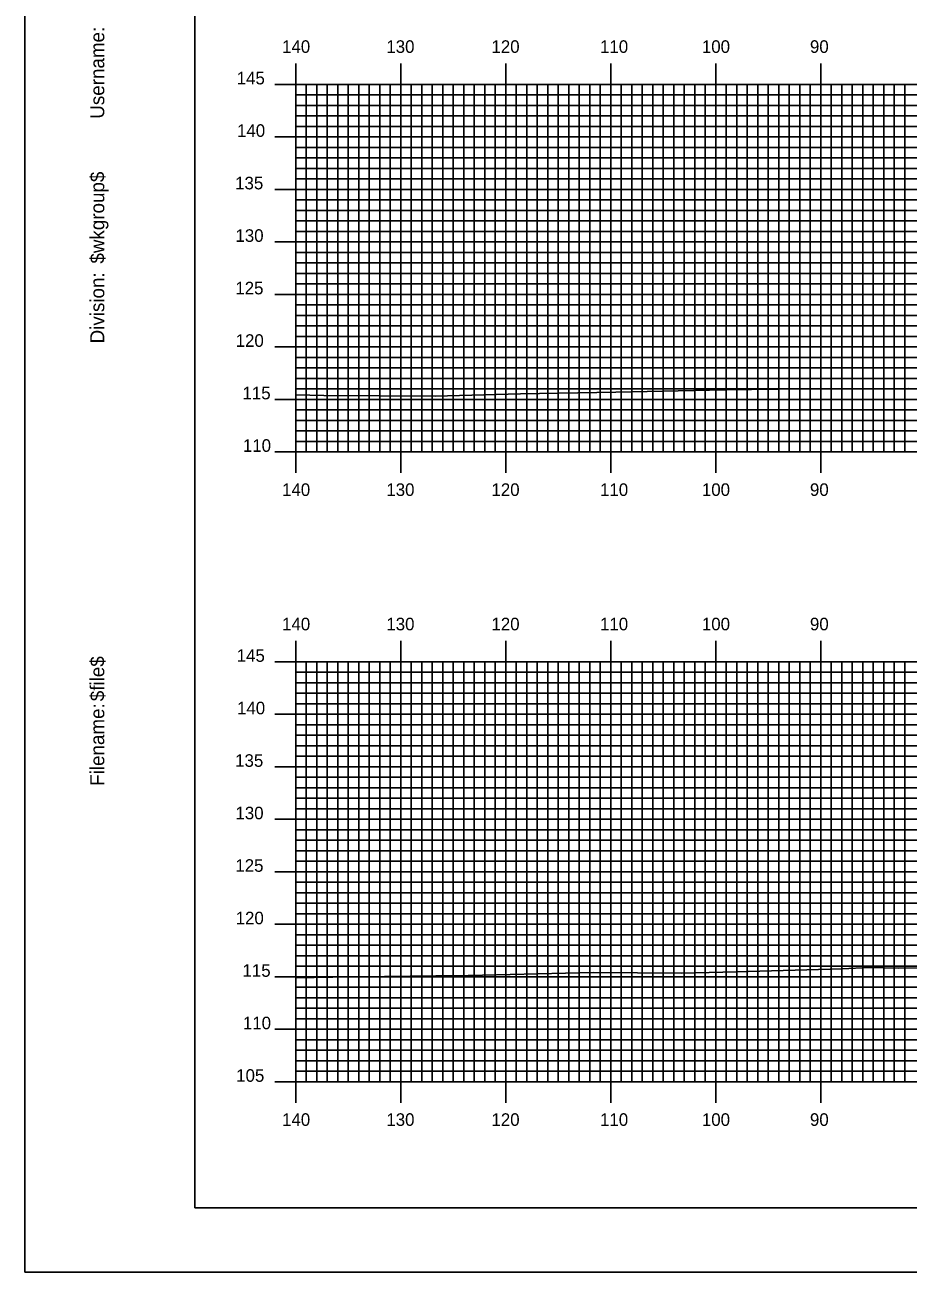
# Model space of a CAD drawing. Extents: x 1789337 to 1789680, y 442591 to 442811.
# Drawn here: x 1789336.9 to 1789421, y 442590.5 to 442709.3 of the extents above; entities that cross this region are included whole.
import ezdxf

# ---------------------------------------------------------------- set-up
doc = ezdxf.new("R2010")
doc.units = 0
for name, color, linetype in [('BORDER', 7, 'Continuous'), ('H_V ANNOTATION', 7, 'Continuous'), ('MAJOR', 7, 'Continuous'), ('MINOR', 7, 'Continuous'), ('PLOT BOUNDARY', 7, 'Continuous'), ('S_Roadway_Centerline', 7, 'Continuous')]:
    doc.layers.add(name, color=color, linetype=linetype)

msp = doc.modelspace()

# ---------------------------------------------------------------- linework, layer by layer
at = {"layer": 'BORDER'}
msp.add_lwpolyline([(1789353.07, 442596.67), (1789673.07, 442596.67), (1789673.07, 442806.67), (1789353.07, 442806.67)], close=True, dxfattribs=at)
at = {"layer": 'MAJOR'}
for p, q in [((1789362.67, 442705.67), (1789362.67, 442703.67)), ((1789372.67, 442705.67), (1789372.67, 442703.67)), ((1789382.67, 442705.67), (1789382.67, 442703.67)), ((1789392.67, 442705.67), (1789392.67, 442703.67)), ((1789402.67, 442705.67), (1789402.67, 442703.67)), ((1789412.67, 442705.67), (1789412.67, 442703.67)), ((1789360.67, 442703.67), (1789362.67, 442703.67)), ((1789362.67, 442703.67), (1789642.67, 442703.67)), ((1789362.67, 442668.67), (1789362.67, 442703.67)), ((1789362.67, 442668.67), (1789362.67, 442703.67)), ((1789362.67, 442703.67), (1789642.67, 442703.67)), ((1789372.67, 442668.67), (1789372.67, 442703.67)), ((1789382.67, 442668.67), (1789382.67, 442703.67)), ((1789392.67, 442668.67), (1789392.67, 442703.67)), ((1789402.67, 442668.67), (1789402.67, 442703.67)), ((1789412.67, 442668.67), (1789412.67, 442703.67)), ((1789360.67, 442698.67), (1789362.67, 442698.67)), ((1789362.67, 442698.67), (1789642.67, 442698.67)), ((1789360.67, 442693.67), (1789362.67, 442693.67)), ((1789362.67, 442693.67), (1789642.67, 442693.67)), ((1789360.67, 442688.67), (1789362.67, 442688.67)), ((1789362.67, 442688.67), (1789642.67, 442688.67)), ((1789360.67, 442683.67), (1789362.67, 442683.67)), ((1789362.67, 442683.67), (1789642.67, 442683.67)), ((1789360.67, 442678.67), (1789362.67, 442678.67)), ((1789362.67, 442678.67), (1789642.67, 442678.67)), ((1789360.67, 442673.67), (1789362.67, 442673.67)), ((1789362.67, 442673.67), (1789642.67, 442673.67)), ((1789360.67, 442668.67), (1789362.67, 442668.67)), ((1789362.67, 442668.67), (1789642.67, 442668.67)), ((1789362.67, 442668.67), (1789642.67, 442668.67)), ((1789362.67, 442666.66), (1789362.67, 442668.67)), ((1789372.67, 442666.66), (1789372.67, 442668.67)), ((1789382.67, 442666.66), (1789382.67, 442668.67)), ((1789392.67, 442666.66), (1789392.67, 442668.67)), ((1789402.67, 442666.66), (1789402.67, 442668.67)), ((1789412.67, 442666.66), (1789412.67, 442668.67)), ((1789362.67, 442650.67), (1789362.67, 442648.67)), ((1789372.67, 442650.67), (1789372.67, 442648.67)), ((1789382.67, 442650.67), (1789382.67, 442648.67)), ((1789392.67, 442650.67), (1789392.67, 442648.67)), ((1789402.67, 442650.67), (1789402.67, 442648.67)), ((1789412.67, 442650.67), (1789412.67, 442648.67)), ((1789360.67, 442648.67), (1789362.67, 442648.67)), ((1789362.67, 442648.67), (1789642.67, 442648.67)), ((1789362.67, 442608.67), (1789362.67, 442648.67)), ((1789362.67, 442608.67), (1789362.67, 442648.67)), ((1789362.67, 442648.67), (1789642.67, 442648.67)), ((1789372.67, 442608.67), (1789372.67, 442648.67)), ((1789382.67, 442608.67), (1789382.67, 442648.67)), ((1789392.67, 442608.67), (1789392.67, 442648.67)), ((1789402.67, 442608.67), (1789402.67, 442648.67)), ((1789412.67, 442608.67), (1789412.67, 442648.67)), ((1789360.67, 442643.67), (1789362.67, 442643.67)), ((1789362.67, 442643.67), (1789642.67, 442643.67)), ((1789360.67, 442638.67), (1789362.67, 442638.67)), ((1789362.67, 442638.67), (1789642.67, 442638.67)), ((1789360.67, 442633.67), (1789362.67, 442633.67)), ((1789362.67, 442633.67), (1789642.67, 442633.67)), ((1789360.67, 442628.67), (1789362.67, 442628.67)), ((1789362.67, 442628.67), (1789642.67, 442628.67)), ((1789360.67, 442623.67), (1789362.67, 442623.67)), ((1789362.67, 442623.67), (1789642.67, 442623.67)), ((1789360.67, 442618.67), (1789362.67, 442618.67)), ((1789362.67, 442618.67), (1789642.67, 442618.67)), ((1789360.67, 442613.67), (1789362.67, 442613.67)), ((1789362.67, 442613.67), (1789642.67, 442613.67)), ((1789360.67, 442608.67), (1789362.67, 442608.67)), ((1789362.67, 442608.67), (1789642.67, 442608.67)), ((1789362.67, 442608.67), (1789642.67, 442608.67)), ((1789362.67, 442606.66), (1789362.67, 442608.67)), ((1789372.67, 442606.66), (1789372.67, 442608.67)), ((1789382.67, 442606.66), (1789382.67, 442608.67)), ((1789392.67, 442606.66), (1789392.67, 442608.67)), ((1789402.67, 442606.66), (1789402.67, 442608.67)), ((1789412.67, 442606.66), (1789412.67, 442608.67))]:
    msp.add_line(p, q, dxfattribs=at)
at = {"layer": 'MINOR'}
for p, q in [((1789362.67, 442702.67), (1789642.67, 442702.67)), ((1789362.67, 442702.67), (1789364.67, 442702.67)), ((1789363.67, 442668.67), (1789363.67, 442703.67)), ((1789364.67, 442668.67), (1789364.67, 442703.67)), ((1789365.67, 442668.67), (1789365.67, 442703.67)), ((1789366.67, 442668.67), (1789366.67, 442703.67)), ((1789367.67, 442668.67), (1789367.67, 442703.67)), ((1789368.67, 442668.67), (1789368.67, 442703.67)), ((1789369.67, 442668.67), (1789369.67, 442703.67)), ((1789370.67, 442668.67), (1789370.67, 442703.67)), ((1789371.67, 442668.67), (1789371.67, 442703.67)), ((1789373.67, 442668.67), (1789373.67, 442703.67)), ((1789374.67, 442668.67), (1789374.67, 442703.67)), ((1789375.67, 442668.67), (1789375.67, 442703.67)), ((1789376.67, 442668.67), (1789376.67, 442703.67)), ((1789377.67, 442668.67), (1789377.67, 442703.67)), ((1789378.67, 442668.67), (1789378.67, 442703.67)), ((1789379.67, 442668.67), (1789379.67, 442703.67)), ((1789380.67, 442668.67), (1789380.67, 442703.67)), ((1789381.67, 442668.67), (1789381.67, 442703.67)), ((1789383.67, 442668.67), (1789383.67, 442703.67)), ((1789384.67, 442668.67), (1789384.67, 442703.67)), ((1789385.67, 442668.67), (1789385.67, 442703.67)), ((1789386.67, 442668.67), (1789386.67, 442703.67)), ((1789387.67, 442668.67), (1789387.67, 442703.67)), ((1789388.67, 442668.67), (1789388.67, 442703.67)), ((1789389.67, 442668.67), (1789389.67, 442703.67)), ((1789390.67, 442668.67), (1789390.67, 442703.67)), ((1789391.67, 442668.67), (1789391.67, 442703.67)), ((1789393.67, 442668.67), (1789393.67, 442703.67)), ((1789394.67, 442668.67), (1789394.67, 442703.67)), ((1789395.67, 442668.67), (1789395.67, 442703.67)), ((1789396.67, 442668.67), (1789396.67, 442703.67)), ((1789397.67, 442668.67), (1789397.67, 442703.67)), ((1789398.67, 442668.67), (1789398.67, 442703.67)), ((1789399.67, 442668.67), (1789399.67, 442703.67)), ((1789400.67, 442668.67), (1789400.67, 442703.67)), ((1789401.67, 442668.67), (1789401.67, 442703.67)), ((1789403.67, 442668.67), (1789403.67, 442703.67)), ((1789404.67, 442668.67), (1789404.67, 442703.67)), ((1789405.67, 442668.67), (1789405.67, 442703.67)), ((1789406.67, 442668.67), (1789406.67, 442703.67)), ((1789407.67, 442668.67), (1789407.67, 442703.67)), ((1789408.67, 442668.67), (1789408.67, 442703.67)), ((1789409.67, 442668.67), (1789409.67, 442703.67)), ((1789410.67, 442668.67), (1789410.67, 442703.67)), ((1789411.67, 442668.67), (1789411.67, 442703.67)), ((1789413.67, 442668.67), (1789413.67, 442703.67)), ((1789414.67, 442668.67), (1789414.67, 442703.67)), ((1789415.67, 442668.67), (1789415.67, 442703.67)), ((1789416.67, 442668.67), (1789416.67, 442703.67)), ((1789417.67, 442668.67), (1789417.67, 442703.67)), ((1789418.67, 442668.67), (1789418.67, 442703.67)), ((1789419.67, 442668.67), (1789419.67, 442703.67)), ((1789420.67, 442668.67), (1789420.67, 442703.67)), ((1789362.67, 442701.67), (1789642.67, 442701.67)), ((1789362.67, 442701.67), (1789364.67, 442701.67)), ((1789362.67, 442700.67), (1789642.67, 442700.67)), ((1789362.67, 442700.67), (1789364.67, 442700.67)), ((1789362.67, 442699.67), (1789642.67, 442699.67)), ((1789362.67, 442699.67), (1789364.67, 442699.67)), ((1789362.67, 442697.67), (1789642.67, 442697.67)), ((1789362.67, 442697.67), (1789364.67, 442697.67)), ((1789362.67, 442696.67), (1789642.67, 442696.67)), ((1789362.67, 442696.67), (1789364.67, 442696.67)), ((1789362.67, 442695.67), (1789642.67, 442695.67)), ((1789362.67, 442695.67), (1789364.67, 442695.67)), ((1789362.67, 442694.67), (1789642.67, 442694.67)), ((1789362.67, 442694.67), (1789364.67, 442694.67)), ((1789362.67, 442692.67), (1789642.67, 442692.67)), ((1789362.67, 442692.67), (1789364.67, 442692.67)), ((1789362.67, 442691.67), (1789642.67, 442691.67)), ((1789362.67, 442691.67), (1789364.67, 442691.67)), ((1789362.67, 442690.67), (1789642.67, 442690.67)), ((1789362.67, 442690.67), (1789364.67, 442690.67)), ((1789362.67, 442689.67), (1789642.67, 442689.67)), ((1789362.67, 442689.67), (1789364.67, 442689.67)), ((1789362.67, 442687.67), (1789642.67, 442687.67)), ((1789362.67, 442687.67), (1789364.67, 442687.67)), ((1789362.67, 442686.67), (1789642.67, 442686.67)), ((1789362.67, 442686.67), (1789364.67, 442686.67)), ((1789362.67, 442685.67), (1789642.67, 442685.67)), ((1789362.67, 442685.67), (1789364.67, 442685.67)), ((1789362.67, 442684.67), (1789642.67, 442684.67)), ((1789362.67, 442684.67), (1789364.67, 442684.67)), ((1789362.67, 442682.67), (1789642.67, 442682.67)), ((1789362.67, 442682.67), (1789364.67, 442682.67)), ((1789362.67, 442681.67), (1789642.67, 442681.67)), ((1789362.67, 442681.67), (1789364.67, 442681.67)), ((1789362.67, 442680.67), (1789642.67, 442680.67)), ((1789362.67, 442680.67), (1789364.67, 442680.67)), ((1789362.67, 442679.67), (1789642.67, 442679.67)), ((1789362.67, 442679.67), (1789364.67, 442679.67)), ((1789362.67, 442677.67), (1789642.67, 442677.67)), ((1789362.67, 442677.67), (1789364.67, 442677.67)), ((1789362.67, 442676.67), (1789642.67, 442676.67)), ((1789362.67, 442676.67), (1789364.67, 442676.67)), ((1789362.67, 442675.67), (1789642.67, 442675.67)), ((1789362.67, 442675.67), (1789364.67, 442675.67)), ((1789362.67, 442674.67), (1789642.67, 442674.67)), ((1789362.67, 442674.67), (1789364.67, 442674.67)), ((1789362.67, 442672.67), (1789642.67, 442672.67)), ((1789362.67, 442672.67), (1789364.67, 442672.67)), ((1789362.67, 442671.67), (1789642.67, 442671.67)), ((1789362.67, 442671.67), (1789364.67, 442671.67)), ((1789362.67, 442670.67), (1789642.67, 442670.67)), ((1789362.67, 442670.67), (1789364.67, 442670.67)), ((1789362.67, 442669.67), (1789642.67, 442669.67)), ((1789362.67, 442669.67), (1789364.67, 442669.67)), ((1789363.67, 442608.67), (1789363.67, 442648.67)), ((1789364.67, 442608.67), (1789364.67, 442648.67)), ((1789365.67, 442608.67), (1789365.67, 442648.67)), ((1789366.67, 442608.67), (1789366.67, 442648.67)), ((1789367.67, 442608.67), (1789367.67, 442648.67)), ((1789368.67, 442608.67), (1789368.67, 442648.67)), ((1789369.67, 442608.67), (1789369.67, 442648.67)), ((1789370.67, 442608.67), (1789370.67, 442648.67)), ((1789371.67, 442608.67), (1789371.67, 442648.67)), ((1789373.67, 442608.67), (1789373.67, 442648.67)), ((1789374.67, 442608.67), (1789374.67, 442648.67)), ((1789375.67, 442608.67), (1789375.67, 442648.67)), ((1789376.67, 442608.67), (1789376.67, 442648.67)), ((1789377.67, 442608.67), (1789377.67, 442648.67)), ((1789378.67, 442608.67), (1789378.67, 442648.67)), ((1789379.67, 442608.67), (1789379.67, 442648.67)), ((1789380.67, 442608.67), (1789380.67, 442648.67)), ((1789381.67, 442608.67), (1789381.67, 442648.67)), ((1789383.67, 442608.67), (1789383.67, 442648.67)), ((1789384.67, 442608.67), (1789384.67, 442648.67)), ((1789385.67, 442608.67), (1789385.67, 442648.67)), ((1789386.67, 442608.67), (1789386.67, 442648.67)), ((1789387.67, 442608.67), (1789387.67, 442648.67)), ((1789388.67, 442608.67), (1789388.67, 442648.67)), ((1789389.67, 442608.67), (1789389.67, 442648.67)), ((1789390.67, 442608.67), (1789390.67, 442648.67)), ((1789391.67, 442608.67), (1789391.67, 442648.67)), ((1789393.67, 442608.67), (1789393.67, 442648.67)), ((1789394.67, 442608.67), (1789394.67, 442648.67)), ((1789395.67, 442608.67), (1789395.67, 442648.67)), ((1789396.67, 442608.67), (1789396.67, 442648.67)), ((1789397.67, 442608.67), (1789397.67, 442648.67)), ((1789398.67, 442608.67), (1789398.67, 442648.67)), ((1789399.67, 442608.67), (1789399.67, 442648.67)), ((1789400.67, 442608.67), (1789400.67, 442648.67)), ((1789401.67, 442608.67), (1789401.67, 442648.67)), ((1789403.67, 442608.67), (1789403.67, 442648.67)), ((1789404.67, 442608.67), (1789404.67, 442648.67)), ((1789405.67, 442608.67), (1789405.67, 442648.67)), ((1789406.67, 442608.67), (1789406.67, 442648.67)), ((1789407.67, 442608.67), (1789407.67, 442648.67)), ((1789408.67, 442608.67), (1789408.67, 442648.67)), ((1789409.67, 442608.67), (1789409.67, 442648.67)), ((1789410.67, 442608.67), (1789410.67, 442648.67)), ((1789411.67, 442608.67), (1789411.67, 442648.67)), ((1789413.67, 442608.67), (1789413.67, 442648.67)), ((1789414.67, 442608.67), (1789414.67, 442648.67)), ((1789415.67, 442608.67), (1789415.67, 442648.67)), ((1789416.67, 442608.67), (1789416.67, 442648.67)), ((1789417.67, 442608.67), (1789417.67, 442648.67)), ((1789418.67, 442608.67), (1789418.67, 442648.67)), ((1789419.67, 442608.67), (1789419.67, 442648.67)), ((1789420.67, 442608.67), (1789420.67, 442648.67)), ((1789362.67, 442647.67), (1789642.67, 442647.67)), ((1789362.67, 442647.67), (1789364.67, 442647.67)), ((1789362.67, 442646.67), (1789642.67, 442646.67)), ((1789362.67, 442646.67), (1789364.67, 442646.67)), ((1789362.67, 442645.67), (1789642.67, 442645.67)), ((1789362.67, 442645.67), (1789364.67, 442645.67)), ((1789362.67, 442644.67), (1789642.67, 442644.67)), ((1789362.67, 442644.67), (1789364.67, 442644.67)), ((1789362.67, 442642.67), (1789642.67, 442642.67)), ((1789362.67, 442642.67), (1789364.67, 442642.67)), ((1789362.67, 442641.67), (1789642.67, 442641.67)), ((1789362.67, 442641.67), (1789364.67, 442641.67)), ((1789362.67, 442640.67), (1789642.67, 442640.67)), ((1789362.67, 442640.67), (1789364.67, 442640.67)), ((1789362.67, 442639.67), (1789642.67, 442639.67)), ((1789362.67, 442639.67), (1789364.67, 442639.67)), ((1789362.67, 442637.67), (1789642.67, 442637.67)), ((1789362.67, 442637.67), (1789364.67, 442637.67)), ((1789362.67, 442636.67), (1789642.67, 442636.67)), ((1789362.67, 442636.67), (1789364.67, 442636.67)), ((1789362.67, 442635.67), (1789642.67, 442635.67)), ((1789362.67, 442635.67), (1789364.67, 442635.67)), ((1789362.67, 442634.67), (1789642.67, 442634.67)), ((1789362.67, 442634.67), (1789364.67, 442634.67)), ((1789362.67, 442632.67), (1789642.67, 442632.67)), ((1789362.67, 442632.67), (1789364.67, 442632.67)), ((1789362.67, 442631.67), (1789642.67, 442631.67)), ((1789362.67, 442631.67), (1789364.67, 442631.67)), ((1789362.67, 442630.67), (1789642.67, 442630.67)), ((1789362.67, 442630.67), (1789364.67, 442630.67)), ((1789362.67, 442629.67), (1789642.67, 442629.67)), ((1789362.67, 442629.67), (1789364.67, 442629.67)), ((1789362.67, 442627.67), (1789642.67, 442627.67)), ((1789362.67, 442627.67), (1789364.67, 442627.67)), ((1789362.67, 442626.67), (1789642.67, 442626.67)), ((1789362.67, 442626.67), (1789364.67, 442626.67)), ((1789362.67, 442625.67), (1789642.67, 442625.67)), ((1789362.67, 442625.67), (1789364.67, 442625.67)), ((1789362.67, 442624.67), (1789642.67, 442624.67)), ((1789362.67, 442624.67), (1789364.67, 442624.67)), ((1789362.67, 442622.67), (1789642.67, 442622.67)), ((1789362.67, 442622.67), (1789364.67, 442622.67)), ((1789362.67, 442621.67), (1789642.67, 442621.67)), ((1789362.67, 442621.67), (1789364.67, 442621.67)), ((1789362.67, 442620.67), (1789642.67, 442620.67)), ((1789362.67, 442620.67), (1789364.67, 442620.67)), ((1789362.67, 442619.67), (1789642.67, 442619.67)), ((1789362.67, 442619.67), (1789364.67, 442619.67)), ((1789362.67, 442617.67), (1789642.67, 442617.67)), ((1789362.67, 442617.67), (1789364.67, 442617.67)), ((1789362.67, 442616.67), (1789642.67, 442616.67)), ((1789362.67, 442616.67), (1789364.67, 442616.67)), ((1789362.67, 442615.67), (1789642.67, 442615.67)), ((1789362.67, 442615.67), (1789364.67, 442615.67)), ((1789362.67, 442614.67), (1789642.67, 442614.67)), ((1789362.67, 442614.67), (1789364.67, 442614.67)), ((1789362.67, 442612.67), (1789642.67, 442612.67)), ((1789362.67, 442612.67), (1789364.67, 442612.67)), ((1789362.67, 442611.67), (1789642.67, 442611.67)), ((1789362.67, 442611.67), (1789364.67, 442611.67)), ((1789362.67, 442610.67), (1789642.67, 442610.67)), ((1789362.67, 442610.67), (1789364.67, 442610.67)), ((1789362.67, 442609.67), (1789642.67, 442609.67)), ((1789362.67, 442609.67), (1789364.67, 442609.67))]:
    msp.add_line(p, q, dxfattribs=at)
at = {"layer": 'PLOT BOUNDARY'}
msp.add_lwpolyline([(1789336.88, 442590.55), (1789676.88, 442590.55), (1789676.88, 442810.55), (1789336.88, 442810.55)], close=True, dxfattribs=at)
at = {"layer": 'S_Roadway_Centerline'}
for points in [[(1789362.67, 442674.09), (1789365.34, 442674.03), (1789375.96, 442673.98), (1789384.08, 442674.19), (1789393.15, 442674.36), (1789403.57, 442674.57), (1789411.11, 442674.68), (1789421.04, 442674.71)], [(1789362.67, 442618.58), (1789366.2, 442618.63), (1789376.02, 442618.76), (1789379.08, 442618.8), (1789380.46, 442618.84), (1789391, 442619.08), (1789399.43, 442619.02), (1789404.66, 442619.13), (1789414.67, 442619.43), (1789417.3, 442619.54), (1789420.04, 442619.5), (1789434.91, 442619.54)]]:
    msp.add_lwpolyline(points, dxfattribs=at)

# ---------------------------------------------------------------- texts
at = {"layer": 'BORDER'}
for s, p in [('Username:', (1789344.44, 442700.4)), ('$wkgroup$', (1789344.44, 442686.6)), ('Division:', (1789344.44, 442679)), ('$file$', (1789344.44, 442644.92)), ('Filename:', (1789344.44, 442636.86))]:
    msp.add_text(s, height=1.339, rotation=90, dxfattribs=at).set_placement(p)
at = {"layer": 'H_V ANNOTATION'}
for s, p in [('140', (1789361.37, 442706.67)), ('130', (1789371.3, 442706.67)), ('120', (1789381.31, 442706.67)), ('110', (1789391.65, 442706.67)), ('100', (1789401.35, 442706.67)), ('90', (1789411.64, 442706.67)), ('145', (1789357.05, 442703.67)), ('140', (1789357.08, 442698.67)), ('135', (1789356.9, 442693.67)), ('130', (1789356.93, 442688.67)), ('125', (1789356.92, 442683.67)), ('120', (1789356.95, 442678.67)), ('115', (1789357.6, 442673.67)), ('110', (1789357.64, 442668.67)), ('140', (1789361.37, 442664.47)), ('130', (1789371.3, 442664.47)), ('120', (1789381.31, 442664.47)), ('110', (1789391.65, 442664.47)), ('100', (1789401.35, 442664.47)), ('90', (1789411.64, 442664.47)), ('140', (1789361.37, 442651.67)), ('130', (1789371.3, 442651.67)), ('120', (1789381.31, 442651.67)), ('110', (1789391.65, 442651.67)), ('100', (1789401.35, 442651.67)), ('90', (1789411.64, 442651.67)), ('145', (1789357.05, 442648.67)), ('140', (1789357.08, 442643.67)), ('135', (1789356.9, 442638.67)), ('130', (1789356.93, 442633.67)), ('125', (1789356.92, 442628.67)), ('120', (1789356.95, 442623.67)), ('115', (1789357.6, 442618.67)), ('110', (1789357.64, 442613.67)), ('105', (1789357, 442608.67)), ('140', (1789361.37, 442604.47)), ('130', (1789371.3, 442604.47)), ('120', (1789381.31, 442604.47)), ('110', (1789391.65, 442604.47)), ('100', (1789401.35, 442604.47)), ('90', (1789411.64, 442604.47))]:
    msp.add_text(s, height=1.2, dxfattribs=at).set_placement(p)
at = {"layer": 'MAJOR'}
for p in [(1789362.66, 442668.67), (1789362.66, 442608.67)]:
    msp.add_text('-', height=0.012, dxfattribs=at).set_placement(p)

doc.saveas('drawing.dxf')
